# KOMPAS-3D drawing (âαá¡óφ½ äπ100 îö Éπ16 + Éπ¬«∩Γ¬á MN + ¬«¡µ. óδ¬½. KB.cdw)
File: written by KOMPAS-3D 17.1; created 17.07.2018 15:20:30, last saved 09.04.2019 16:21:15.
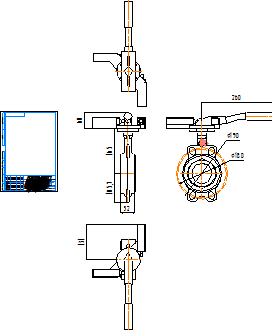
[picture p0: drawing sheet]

Sheet 1: A4, portrait

Title block, sheet 1: name: Гранвэл Ду100 МФ Ру16 + / Рукоятка MN + конц. выкл. KB; material: Внимание! Данный продукт является объектом авторского права ООО «Торговый Дом АДЛ». / Запрещается изменение, копирование, распространение / (в том числе путем копирования на другие сайты и ресурсы в Интернете) / или любое иное использование информации и объектов без предварительного / согласия правообладателя (ООО «Торговый Дом АДЛ»).; mass: 8,8; sheets: 1; organisation: ООО "Торговый дом АДЛ"; sheet format: A4; stored path: \\adlc.lan\data\АДЛ_ПКД\3D-модели\ADL production\Дисковые поворотные затворы ГРАНВЭЛ\межфланцевый с рукояткой MN и конц. выкл\KOMPAS 2D\Гранвэл Ду100 МФ Ру16 + Рукоятка MN + конц. выкл. KB.cdw

Views: Вид 1, Проекционный вид 2, Проекционный вид 3, Проекционный вид 4
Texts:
  kka
  adl
Dimensions and other numbers on the sheet: 105,7; 165; 52; 60; 131; 190; 180; 260; 1:1; 1; 8,8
